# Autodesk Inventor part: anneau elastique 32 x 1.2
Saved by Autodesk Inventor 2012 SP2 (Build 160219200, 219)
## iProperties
Created: 2013-04
Part Number: anneau elastique 32 x 1.2
Material: Default
Document SubType Name: Modeling
Designer: papa
Density: 1 g/cm^3
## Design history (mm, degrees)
node "anneau elastique 32 x 1.21"
node "anneau elastique 32 x 1.2"
node "Base1"
